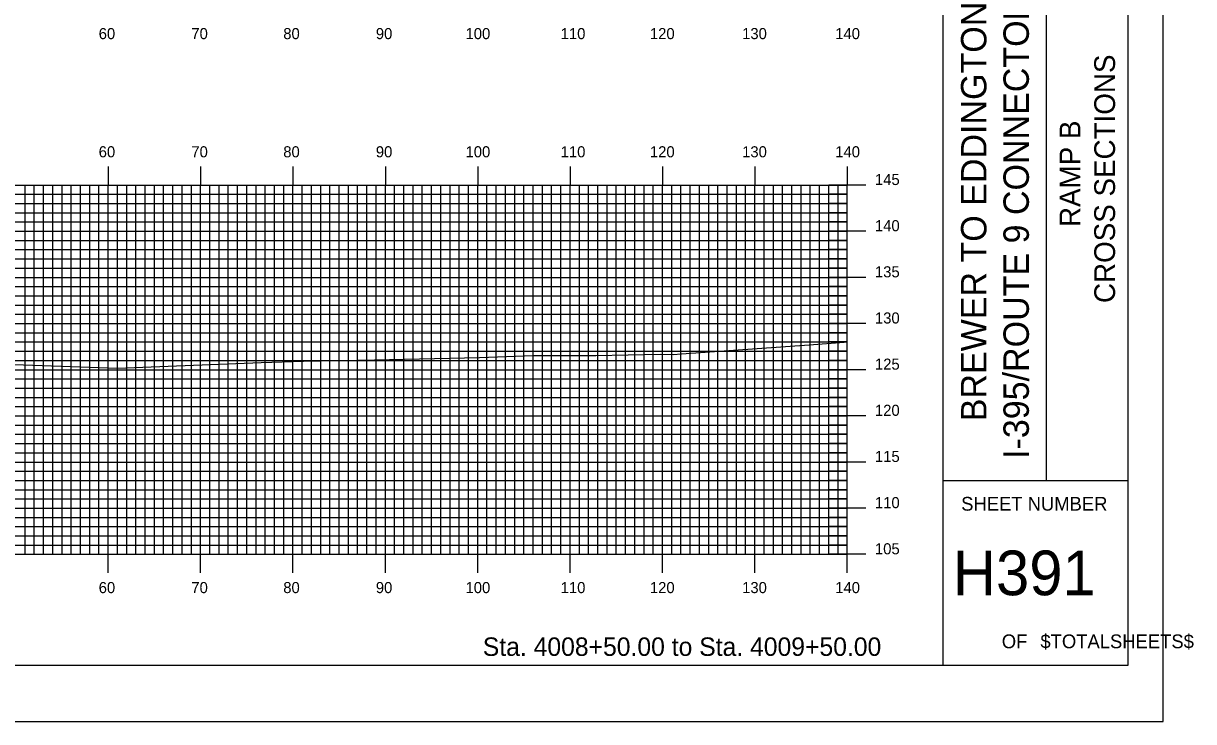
# Model space of a CAD drawing. Extents: x 852147 to 852490, y 364661 to 364881.
# Drawn here: x 852363.6 to 852490.3, y 364661.3 to 364736.9 of the extents above; entities that cross this region are included whole.
import ezdxf

# ---------------------------------------------------------------- set-up
doc = ezdxf.new("R2010")
doc.units = 0
for name, color, linetype in [('BORDER', 7, 'Continuous'), ('H_V ANNOTATION', 7, 'Continuous'), ('MAJOR', 7, 'Continuous'), ('MINOR', 7, 'Continuous'), ('PLOT BOUNDARY', 7, 'Continuous'), ('S_Roadway_Centerline', 7, 'Continuous')]:
    doc.layers.add(name, color=color, linetype=linetype)

msp = doc.modelspace()

# ---------------------------------------------------------------- linework, layer by layer
at = {"layer": 'BORDER'}
for p, q in [((852463.16, 364667.37), (852463.16, 364877.37)), ((852474.34, 364687.38), (852474.34, 364757.38)), ((852463.16, 364687.38), (852483.16, 364687.38))]:
    msp.add_line(p, q, dxfattribs=at)
msp.add_lwpolyline([(852163.16, 364667.37), (852483.16, 364667.37), (852483.16, 364877.37), (852163.16, 364877.37)], close=True, dxfattribs=at)
at = {"layer": 'MAJOR'}
for p, q in [((852372.76, 364721.37), (852372.76, 364719.37)), ((852382.76, 364721.37), (852382.76, 364719.37)), ((852392.76, 364721.37), (852392.76, 364719.37)), ((852402.76, 364721.37), (852402.76, 364719.37)), ((852412.76, 364721.37), (852412.76, 364719.37)), ((852422.76, 364721.37), (852422.76, 364719.37)), ((852432.76, 364721.37), (852432.76, 364719.37)), ((852442.76, 364721.37), (852442.76, 364719.37)), ((852452.76, 364721.37), (852452.76, 364719.37)), ((852172.76, 364719.37), (852452.76, 364719.37)), ((852172.76, 364719.37), (852452.76, 364719.37)), ((852372.76, 364679.37), (852372.76, 364719.37)), ((852382.76, 364679.37), (852382.76, 364719.37)), ((852392.76, 364679.37), (852392.76, 364719.37)), ((852402.76, 364679.37), (852402.76, 364719.37)), ((852412.76, 364679.37), (852412.76, 364719.37)), ((852422.76, 364679.37), (852422.76, 364719.37)), ((852432.76, 364679.37), (852432.76, 364719.37)), ((852442.76, 364679.37), (852442.76, 364719.37)), ((852454.76, 364719.37), (852450.75, 364719.37)), ((852452.76, 364679.37), (852452.76, 364719.37)), ((852452.76, 364679.37), (852452.76, 364719.37)), ((852172.76, 364714.37), (852452.76, 364714.37)), ((852454.76, 364714.37), (852450.75, 364714.37)), ((852172.76, 364709.37), (852452.76, 364709.37)), ((852454.76, 364709.37), (852450.75, 364709.37)), ((852172.76, 364704.37), (852452.76, 364704.37)), ((852454.76, 364704.37), (852450.75, 364704.37)), ((852172.76, 364699.37), (852452.76, 364699.37)), ((852454.76, 364699.37), (852450.75, 364699.37)), ((852172.76, 364694.37), (852452.76, 364694.37)), ((852454.76, 364694.37), (852450.75, 364694.37)), ((852172.76, 364689.37), (852452.76, 364689.37)), ((852454.76, 364689.37), (852450.75, 364689.37)), ((852172.76, 364684.37), (852452.76, 364684.37)), ((852454.76, 364684.37), (852450.75, 364684.37)), ((852172.76, 364679.37), (852452.76, 364679.37)), ((852172.76, 364679.37), (852452.76, 364679.37)), ((852372.76, 364677.37), (852372.76, 364679.37)), ((852382.76, 364677.37), (852382.76, 364679.37)), ((852392.76, 364677.37), (852392.76, 364679.37)), ((852402.76, 364677.37), (852402.76, 364679.37)), ((852412.76, 364677.37), (852412.76, 364679.37)), ((852422.76, 364677.37), (852422.76, 364679.37)), ((852432.76, 364677.37), (852432.76, 364679.37)), ((852442.76, 364677.37), (852442.76, 364679.37)), ((852454.76, 364679.37), (852450.75, 364679.37)), ((852452.76, 364677.37), (852452.76, 364679.37))]:
    msp.add_line(p, q, dxfattribs=at)
at = {"layer": 'MINOR'}
for p, q in [((852363.76, 364679.37), (852363.76, 364719.37)), ((852364.76, 364679.37), (852364.76, 364719.37)), ((852365.76, 364679.37), (852365.76, 364719.37)), ((852366.76, 364679.37), (852366.76, 364719.37)), ((852367.76, 364679.37), (852367.76, 364719.37)), ((852368.76, 364679.37), (852368.76, 364719.37)), ((852369.76, 364679.37), (852369.76, 364719.37)), ((852370.76, 364679.37), (852370.76, 364719.37)), ((852371.76, 364679.37), (852371.76, 364719.37)), ((852373.76, 364679.37), (852373.76, 364719.37)), ((852374.76, 364679.37), (852374.76, 364719.37)), ((852375.76, 364679.37), (852375.76, 364719.37)), ((852376.76, 364679.37), (852376.76, 364719.37)), ((852377.76, 364679.37), (852377.76, 364719.37)), ((852378.76, 364679.37), (852378.76, 364719.37)), ((852379.76, 364679.37), (852379.76, 364719.37)), ((852380.76, 364679.37), (852380.76, 364719.37)), ((852381.76, 364679.37), (852381.76, 364719.37)), ((852383.76, 364679.37), (852383.76, 364719.37)), ((852384.76, 364679.37), (852384.76, 364719.37)), ((852385.76, 364679.37), (852385.76, 364719.37)), ((852386.76, 364679.37), (852386.76, 364719.37)), ((852387.76, 364679.37), (852387.76, 364719.37)), ((852388.76, 364679.37), (852388.76, 364719.37)), ((852389.76, 364679.37), (852389.76, 364719.37)), ((852390.76, 364679.37), (852390.76, 364719.37)), ((852391.76, 364679.37), (852391.76, 364719.37)), ((852393.76, 364679.37), (852393.76, 364719.37)), ((852394.76, 364679.37), (852394.76, 364719.37)), ((852395.76, 364679.37), (852395.76, 364719.37)), ((852396.76, 364679.37), (852396.76, 364719.37)), ((852397.76, 364679.37), (852397.76, 364719.37)), ((852398.76, 364679.37), (852398.76, 364719.37)), ((852399.76, 364679.37), (852399.76, 364719.37)), ((852400.76, 364679.37), (852400.76, 364719.37)), ((852401.76, 364679.37), (852401.76, 364719.37)), ((852403.76, 364679.37), (852403.76, 364719.37)), ((852404.76, 364679.37), (852404.76, 364719.37)), ((852405.76, 364679.37), (852405.76, 364719.37)), ((852406.76, 364679.37), (852406.76, 364719.37)), ((852407.76, 364679.37), (852407.76, 364719.37)), ((852408.76, 364679.37), (852408.76, 364719.37)), ((852409.76, 364679.37), (852409.76, 364719.37)), ((852410.76, 364679.37), (852410.76, 364719.37)), ((852411.76, 364679.37), (852411.76, 364719.37)), ((852413.76, 364679.37), (852413.76, 364719.37)), ((852414.76, 364679.37), (852414.76, 364719.37)), ((852415.76, 364679.37), (852415.76, 364719.37)), ((852416.76, 364679.37), (852416.76, 364719.37)), ((852417.76, 364679.37), (852417.76, 364719.37)), ((852418.76, 364679.37), (852418.76, 364719.37)), ((852419.76, 364679.37), (852419.76, 364719.37)), ((852420.76, 364679.37), (852420.76, 364719.37)), ((852421.76, 364679.37), (852421.76, 364719.37)), ((852423.76, 364679.37), (852423.76, 364719.37)), ((852424.76, 364679.37), (852424.76, 364719.37)), ((852425.76, 364679.37), (852425.76, 364719.37)), ((852426.76, 364679.37), (852426.76, 364719.37)), ((852427.76, 364679.37), (852427.76, 364719.37)), ((852428.76, 364679.37), (852428.76, 364719.37)), ((852429.76, 364679.37), (852429.76, 364719.37)), ((852430.76, 364679.37), (852430.76, 364719.37)), ((852431.76, 364679.37), (852431.76, 364719.37)), ((852433.76, 364679.37), (852433.76, 364719.37)), ((852434.76, 364679.37), (852434.76, 364719.37)), ((852435.76, 364679.37), (852435.76, 364719.37)), ((852436.76, 364679.37), (852436.76, 364719.37)), ((852437.76, 364679.37), (852437.76, 364719.37)), ((852438.76, 364679.37), (852438.76, 364719.37)), ((852439.76, 364679.37), (852439.76, 364719.37)), ((852440.76, 364679.37), (852440.76, 364719.37)), ((852441.76, 364679.37), (852441.76, 364719.37)), ((852443.76, 364679.37), (852443.76, 364719.37)), ((852444.76, 364679.37), (852444.76, 364719.37)), ((852445.76, 364679.37), (852445.76, 364719.37)), ((852446.76, 364679.37), (852446.76, 364719.37)), ((852447.76, 364679.37), (852447.76, 364719.37)), ((852448.76, 364679.37), (852448.76, 364719.37)), ((852449.76, 364679.37), (852449.76, 364719.37)), ((852450.76, 364679.37), (852450.76, 364719.37)), ((852451.76, 364679.37), (852451.76, 364719.37)), ((852172.76, 364718.37), (852452.76, 364718.37)), ((852452.76, 364718.37), (852450.75, 364718.37)), ((852172.76, 364717.37), (852452.76, 364717.37)), ((852452.76, 364717.37), (852450.75, 364717.37)), ((852172.76, 364716.37), (852452.76, 364716.37)), ((852452.76, 364716.37), (852450.75, 364716.37)), ((852172.76, 364715.37), (852452.76, 364715.37)), ((852452.76, 364715.37), (852450.75, 364715.37)), ((852172.76, 364713.37), (852452.76, 364713.37)), ((852452.76, 364713.37), (852450.75, 364713.37)), ((852172.76, 364712.37), (852452.76, 364712.37)), ((852452.76, 364712.37), (852450.75, 364712.37)), ((852172.76, 364711.37), (852452.76, 364711.37)), ((852452.76, 364711.37), (852450.75, 364711.37)), ((852172.76, 364710.37), (852452.76, 364710.37)), ((852452.76, 364710.37), (852450.75, 364710.37)), ((852172.76, 364708.37), (852452.76, 364708.37)), ((852452.76, 364708.37), (852450.75, 364708.37)), ((852172.76, 364707.37), (852452.76, 364707.37)), ((852452.76, 364707.37), (852450.75, 364707.37)), ((852172.76, 364706.37), (852452.76, 364706.37)), ((852452.76, 364706.37), (852450.75, 364706.37)), ((852172.76, 364705.37), (852452.76, 364705.37)), ((852452.76, 364705.37), (852450.75, 364705.37)), ((852172.76, 364703.37), (852452.76, 364703.37)), ((852452.76, 364703.37), (852450.75, 364703.37)), ((852172.76, 364702.37), (852452.76, 364702.37)), ((852452.76, 364702.37), (852450.75, 364702.37)), ((852172.76, 364701.37), (852452.76, 364701.37)), ((852172.76, 364700.37), (852452.76, 364700.37)), ((852452.76, 364701.37), (852450.75, 364701.37)), ((852452.76, 364700.37), (852450.75, 364700.37)), ((852172.76, 364698.37), (852452.76, 364698.37)), ((852452.76, 364698.37), (852450.75, 364698.37)), ((852172.76, 364697.37), (852452.76, 364697.37)), ((852452.76, 364697.37), (852450.75, 364697.37)), ((852172.76, 364696.37), (852452.76, 364696.37)), ((852172.76, 364695.37), (852452.76, 364695.37)), ((852452.76, 364696.37), (852450.75, 364696.37)), ((852452.76, 364695.37), (852450.75, 364695.37)), ((852172.76, 364693.37), (852452.76, 364693.37)), ((852452.76, 364693.37), (852450.75, 364693.37)), ((852172.76, 364692.37), (852452.76, 364692.37)), ((852452.76, 364692.37), (852450.75, 364692.37)), ((852172.76, 364691.37), (852452.76, 364691.37)), ((852172.76, 364690.37), (852452.76, 364690.37)), ((852452.76, 364691.37), (852450.75, 364691.37)), ((852452.76, 364690.37), (852450.75, 364690.37)), ((852172.76, 364688.37), (852452.76, 364688.37)), ((852452.76, 364688.37), (852450.75, 364688.37)), ((852172.76, 364687.37), (852452.76, 364687.37)), ((852452.76, 364687.37), (852450.75, 364687.37)), ((852172.76, 364686.37), (852452.76, 364686.37)), ((852172.76, 364685.37), (852452.76, 364685.37)), ((852452.76, 364686.37), (852450.75, 364686.37)), ((852452.76, 364685.37), (852450.75, 364685.37)), ((852172.76, 364683.37), (852452.76, 364683.37)), ((852452.76, 364683.37), (852450.75, 364683.37)), ((852172.76, 364682.37), (852452.76, 364682.37)), ((852172.76, 364681.37), (852452.76, 364681.37)), ((852452.76, 364682.37), (852450.75, 364682.37)), ((852452.76, 364681.37), (852450.75, 364681.37)), ((852172.76, 364680.37), (852452.76, 364680.37)), ((852452.76, 364680.37), (852450.75, 364680.37))]:
    msp.add_line(p, q, dxfattribs=at)
at = {"layer": 'PLOT BOUNDARY'}
msp.add_lwpolyline([(852146.97, 364661.25), (852486.97, 364661.25), (852486.97, 364881.25), (852146.97, 364881.25)], close=True, dxfattribs=at)
at = {"layer": 'S_Roadway_Centerline'}
msp.add_lwpolyline([(852360.48, 364700.01), (852373.76, 364699.54), (852389.32, 364700.14), (852393.9, 364700.3), (852401.6, 364700.45), (852412.96, 364700.7), (852418.78, 364700.89), (852425.53, 364700.91), (852432.53, 364701.06), (852433.92, 364701.01), (852434.81, 364701.09), (852448.62, 364702.05), (852452.42, 364702.35), (852452.76, 364702.39)], dxfattribs=at)

# ---------------------------------------------------------------- texts
at = {"layer": 'BORDER'}
for s, height, p in [('I-395/ROUTE 9 CONNECTOR', 2.7557, (852472.42, 364689.7)), ('BREWER TO EDDINGTON', 2.7557, (852467.83, 364693.78)), ('CROSS SECTIONS', 2.25, (852481.75, 364706.59)), ('RAMP B', 2.25, (852478, 364714.82))]:
    msp.add_text(s, height=height, rotation=90, dxfattribs=at).set_placement(p)
for s, height, p in [('SHEET NUMBER', 1.4905, (852465.09, 364684.1)), ('H391', 4.839, (852464.19, 364674.94)), ('OF', 1.491, (852469.49, 364669.2)), ('$TOTALSHEETS$', 1.4905, (852473.67, 364669.2))]:
    msp.add_text(s, height=height, dxfattribs=at).set_placement(p)
at = {"layer": 'H_V ANNOTATION'}
for s, height, p in [('60', 1.2, (852371.73, 364735.17)), ('70', 1.2, (852381.76, 364735.17)), ('80', 1.2, (852391.71, 364735.17)), ('90', 1.2, (852401.73, 364735.17)), ('100', 1.2, (852411.44, 364735.17)), ('110', 1.2, (852421.74, 364735.17)), ('120', 1.2, (852431.4, 364735.17)), ('130', 1.2, (852441.38, 364735.17)), ('140', 1.2, (852451.46, 364735.17)), ('60', 1.2, (852371.73, 364722.37)), ('70', 1.2, (852381.76, 364722.37)), ('80', 1.2, (852391.71, 364722.37)), ('90', 1.2, (852401.73, 364722.37)), ('100', 1.2, (852411.44, 364722.37)), ('110', 1.2, (852421.74, 364722.37)), ('120', 1.2, (852431.4, 364722.37)), ('130', 1.2, (852441.38, 364722.37)), ('140', 1.2, (852451.46, 364722.37)), ('145', 1.2, (852455.76, 364719.37)), ('140', 1.2, (852455.76, 364714.37)), ('135', 1.2, (852455.76, 364709.37)), ('130', 1.2, (852455.76, 364704.37)), ('125', 1.2, (852455.76, 364699.37)), ('120', 1.2, (852455.76, 364694.37)), ('115', 1.2, (852455.76, 364689.37)), ('110', 1.2, (852455.76, 364684.37)), ('105', 1.2, (852455.76, 364679.37)), ('60', 1.2, (852371.73, 364675.17)), ('70', 1.2, (852381.76, 364675.17)), ('80', 1.2, (852391.71, 364675.17)), ('90', 1.2, (852401.73, 364675.17)), ('100', 1.2, (852411.44, 364675.17)), ('110', 1.2, (852421.74, 364675.17)), ('120', 1.2, (852431.4, 364675.17)), ('130', 1.2, (852441.38, 364675.17)), ('140', 1.2, (852451.46, 364675.17)), ('Sta. 4008+50.00 to Sta. 4009+50.00', 2.0004, (852413.31, 364668.37))]:
    msp.add_text(s, height=height, dxfattribs=at).set_placement(p)

doc.saveas('drawing.dxf')
